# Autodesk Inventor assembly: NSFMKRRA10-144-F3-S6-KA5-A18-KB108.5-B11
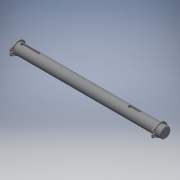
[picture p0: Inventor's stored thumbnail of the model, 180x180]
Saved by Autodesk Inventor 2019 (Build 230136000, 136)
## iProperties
Category: PARTsolutions
Company: MISUMI
Created: 2022-11
Part Number: NSFMKRRA10-144-F3-S6-KA5-A18-KB108.5-B11
Catalog Web Link: www.cadenas.de
Description: NSFMKRR, SFMKRR, PSFMKRR, SSFMKRR, NSFHKRR, SFHKRR, PSFHKRR, SSFHKRR, NSFGKRR, SFGKRR, PSFGKRR, SSFGKRR, NSFMKRRA, SFMKRRA, PSFMKRRA, SSFMKRRA, NSFHKRRA, SFHKRR
Vendor: MISUMI
Document SubType Name: Assembly
Designer: psAdmin
Manufacturer: MISUMI
Mass: 11.263 g
Surface Area: 51.9426 cm^2
Volume: 11.263 cm^3
Density: 1 g/cm^3
Title: NSFMKRRA10-144-F3-S6-KA5-A18-KB108.5-B11
Author: Cadenas PARTsolutions
Comments: Rotary Shafts - Retaining Ring Grooves on Both Ends with Keyway -
PSOL_IDENT_0: {$CADENAS_DATA/23d-libs/misumi/metric/11_rotary_shafts/psfgkrr_asmtab.prj},644 {VTYP=3D},{STYP=ASSTA
PSOL_IDENT_1: B},{NB=NSFMKRRA10-144-F3-S6-KA5-A18-KB108.5-B11},{LINA=NSFMKRRA10-144-F3-S6-KA5-A18-KB108.5-B11},{NN=
PSOL_IDENT_2: NSFMKRR, SFMKRR, PSFMKRR, SSFMKRR, NSFHKRR, SFHKRR, PSFHKRR, SSFHKRR, NSFGKRR, SFGKRR, PSFGKRR, SSFG
PSOL_IDENT_3: KRR, NSFMKRRA, SFMKRRA, PSFMKRRA, SSFMKRRA, NSFHKRRA, SFHKRRA, PSFHKRRA, SSFHKRRA, NSFGKRRA, SFGKRRA
PSOL_IDENT_4: , PSFGKRRA, SSFGKRRA},{DATE=25.01.2022 23:09:58},{GEOMDATE=05.02.2021 08:16:43},{VERSION=},{LINEID=3
PSOL_IDENT_5: 0},{WBVAR=TS,TYS,MAT,ST,ALT1,L,F,S,NOK,KA,A,KB,B,KC,C,ALT3,FC,GALT3,WFC,J,WALT3,V,ALT4,SFC,SG,AG,ALT
PSOL_IDENT_6: 10,KWC,ALT11,WC,ALT5,UC,ALT7,SC,ALT32,CD},{WBNUMERIC=L,F,S,KA,A,KB,B,KC,C,FC,GALT3,WFC,J,WALT3,V,SFC
PSOL_IDENT_7: ,SG,AG,KWC,WC,UC,SC}  {NB=NSFMKRRA10-144-F3-S6-KA5-A18-KB108.5-B11},{LINA=NSFMKRRA10-144-F3-S6-KA5-A
PSOL_IDENT_8: 18-KB108.5-B11},{KT=DUMMY},{PN=NSFMKRRA10-144-F3-S6-KA5-A18-KB108.5-B11},{TS=A},{TSALG='','Standard'
PSOL_IDENT_9: ,'A','Retaining Ring'},{TYS=M},{TYSALG= 'M','h9 (Cold-drawn)','H','h7 (Ground)','G','g6 (Ground)' },
PSOL_IDENT_10: {MAT=S45C},{MATALG= 'S45C','S45C Equivalent', 'SUS304','304 Stainless Steel' },{ST=},{STALG= '','-','
PSOL_IDENT_11: BO','Black Oxide', 'ENP','Electroless Nickel Plating' },{TYPE=NSFMKRR},{D=10},{ALT1=},{LKCMAX=799.9}
PSOL_IDENT_12: ,{L=144.0},{LALG=[15:800/0.1]},{LMIN=15},{LMAX=800},{F=3.0},{FALG=[3:139/0.1]},{FMIN=3},{FMAX1=135.8
PSOL_IDENT_13: },{FMIN2=6.2},{FMAX2=139},{S=6.0},{SALG=[3:139/0.1]},{SMIN1=3},{SMAX1=134},{SMIN2=6.2},{SMAX2=139},{
PSOL_IDENT_14: DD=9.6},{MM=1.15},{MMALG=1.2},{MMJ=2},{NOK=2},{NOKALG= '1', 'with 1 Key Groove', '2'  , 'with 2 Key
PSOL_IDENT_15: Grooves', '3'  , 'with 3 Key Grooves'},{CIFNOK1=0},{CIFNOK2=3},{CIFNOK3=0},{TOL1=0},{TOL2=3},{TOL3=0
PSOL_IDENT_16: },{BB=3},{TT=1.8},{KA=5.0},{KAALG=[5:128/0.1]},{KAMIN1=0},{KAMIN2=5},{KAMIN3=141.2},{KAMAX1=-1000},{
PSOL_IDENT_17: KAMAX2=128},{KAMAX3=-1000},{A=18.0},{AALG=[3:100/0.1]},{AMIN=3},{AMAX=100},{AMAX1=-1000},{AMAX2=100}
PSOL_IDENT_18: ,{AMAX3=-1000},{KAPN=-KA5-A18},{KB=108.5},{KBALG=[25:133/0.1]},{KBMIN1=25},{KBMIN2=25},{KBMIN3=141.2
PSOL_IDENT_19: },{KBMAX1=-1000},{KBMAX2=133},{KBMAX3=-1000},{B=11.0},{BALG=[3:27.5/0.1]},{BMIN=3},{BMAX=27.5},{BMAX
PSOL_IDENT_20: 1=-1000},{BMAX2=27.5},{BMAX3=-1000},{KBPN=-KB108.5-B11},{KC=0.0},{KCALG=[0]},{KCMIN1=121.5},{KCMIN2=
PSOL_IDENT_21: 121.5},{KCMIN3=141.2},{KCMAX1=-1000},{KCMAX2=-1000},{KCMAX3=-1000},{C=0.0},{CALG=0},{CMIN=3},{CMAX=-
PSOL_IDENT_22: 1000},{CMAX1=-1000},{CMAX2=-1000},{CMAX3=-1000},{CIFKA=5},{CIFKB=3},{CIFKC=3},{KCPN=},{ALT3=},{ALT3A
PSOL_IDENT_23: LG= '', 'w/o Set Screw Flat','FC','with FC (Adds a Set Screw Flat)','WFC','with WFC (Adds Two Set Sc
PSOL_IDENT_24: rew Flats)','FCWFC','with FC + WFC (Adds Three Set Screw Flats)' },{ALT3PN=},{FC=0},{FCALG=[0]},{FCM
PSOL_IDENT_25: IN=0},{FCMAX=143},{GALT3=0},{GALT3ALG=[0]},{GALT3MIN=1},{GALT3MAX=70},{GALT3MAX2=70},{GALT3MAX3=70},
PSOL_IDENT_26: {WFC=0},{WFCALG=[0]},{WFCMIN=0},{WFCMIN2=2},{WFCMAX=140},{WFCMAX2=-3},{WFCMAX3=-4},{J=0},{JALG=[0]},
PSOL_IDENT_27: {JMIN=1},{JMAX=70},{JMAX2=-2},{JMAX3=-5},{WALT3=0},{WALT3ALG=[0]},{WALT3MIN=0},{WALT3MIN2=146},{WALT
PSOL_IDENT_28: 3MAX=141},{WALT3MAX2=141},{V=0},{VALG=[0]},{VMIN=1},{VMAX=70},{VMAX2=70},{CIFFC=0},{ALT4=},{ALT4ALG=
PSOL_IDENT_29: '', 'w/o SFC (2 Set Screw Flats (Angle Specified))', 'SFC'  , 'with SFC (2 Set Screw Flats (Angle S
PSOL_IDENT_30: pecified))'},{ALT4PN=},{SFC=0},{SFCALG=[0]},{SFCMIN=0},{SFCMAX=143},{SG=0},{SGALG=[0]},{SGMIN=1},{SG
PSOL_IDENT_31: MAX=70},{AG=0},{AGALG=[0]},{H=0},{CIFSFC=0},{ALT10=},{ALT10ALG= '','Not applicable' },{KWC=0},{KWCAL
PSOL_IDENT_32: G=[0]},{KWCMIN=1},{KWCMAX=0},{WALT10=8},{ALT10PN=},{ALT11=},{ALT11ALG= '','Not applicable' },{WC=0.0
PSOL_IDENT_33: },{WCALG=[0]},{ALT11PN=},{ALT5=},{ALT5ALG= '', 'w/o UC (Slit Cam Groove)', 'UC', 'with UC (Slit Cam
PSOL_IDENT_34: Groove)'},{ALT5PN=},{UC=0},{UCALG=[0]},{UCMIN=1},{UCMAX=138},{DDALT5=0},{LL1=0},{ALT7=},{ALT7ALG= ''
PSOL_IDENT_35: , 'w/o SC (Wrench Flats)', 'SC', 'with SC (Wrench Flats)'},{ALT7PN=},{SC=0},{SCALG=[0]},{SCMIN=0},{S
PSOL_IDENT_36: CMAX=136},{LL2=0},{LL2ALG=8},{WALT7=0},{CIFSC=0},{ALT32=},{ALT32ALG= '','w/o CD (Changes Part D Cham
PSOL_IDENT_37: fering)','CD','with CD (Changes Part D Chamfering)' },{CD=},{CDALG= '','N/A' },{CD3D=0.5},{ALT32PN=}
PSOL_IDENT_38: ,{CIF323R=0},{CIF323L=0},{CIF324R=0},{CIF324L=0},{CIF3210=0},{CIF32F=0},{CIF32S=0},{ERRORPN=},{ERROR
PSOL_IDENT_39: KGALT3=OK},{ERRORKGALT4=OK},{ERRORKGALT5=OK},{ERRORKGALT7=OK},{ERRORKGALT10=OK},{ERRORRALT3=OK},{ERR
PSOL_IDENT_40: ORRALT4=NG},{ERRORRALT5=NG},{ERRORRALT7=NG},{ERRORRALT10=OK},{ERRORALT34=OK},{ERRORALT35=OK},{ERRORA
PSOL_IDENT_41: LT37=OK},{ERRORALT310=OK},{ERRORALT45=OK},{ERRORALT47=OK},{ERRORALT410=OK},{ERRORALT57=OK},{ERRORALT
PSOL_IDENT_42: 510=OK},{ERRORALT710=OK},{PCUT3D=0},{QCUT3D=0},{TTALT2=1.8},{BBALT2=3},{PPATH=11_components/psfgkrr/
PSOL_IDENT_43: psfgkrr_asmtpl.prj}
NB: NSFMKRRA10-144-F3-S6-KA5-A18-KB108.5-B11
NN: NSFMKRR, SFMKRR, PSFMKRR, SSFMKRR, NSFHKRR, SFHKRR, PSFHKRR, SSFHKRR, NSFGKRR, SFGKRR, PSFGKRR, SSFGKRR, NSFMKRRA, SFMKRRA, PSFMKRRA, SSFMKRRA, NSFHKRRA, SFHKRR
NT: Rotary Shafts - Retaining Ring Grooves on Both Ends with Keyway -
NBSYN: $PN.
LINA: NSFMKRRA10-144-F3-S6-KA5-A18-KB108.5-B11
CATALOG: Misumi
PN: NSFMKRRA10-144-F3-S6-KA5-A18-KB108.5-B11
TS: Retaining Ring
TYS: h9 (Cold-drawn)
MAT: S45C Equivalent
ST: -
D: 10
ALT1: w/o LKC (Changes L Tolerance)
L: 144
F: 3
S: 6
DD: 9.6
MM: 1.15
NOK: with 2 Key Grooves
KA: 5
A: 18
KB: 108.5
B: 11
KC: 0
C: 0
ALT3: w/o Set Screw Flat
FC: 0
GALT3: 0
WFC: 0
J: 0
WALT3: 0
V: 0
ALT4: w/o SFC (2 Set Screw Flats (Angle Specified))
SFC: 0
SG: 0
AG: 0
H: 0
ALT10: Not applicable
KWC: 0
ALT11: Not applicable
WC: 0
ALT5: w/o UC (Slit Cam Groove)
UC: 0
DDALT5: 0
LL1: 0
ALT7: w/o SC (Wrench Flats)
SC: 0
LL2: 0
WALT7: 0
ALT32: w/o CD (Changes Part D Chamfering)
CD: N/A
SUPPLIER: MISUMI
ARTICLENO: NSFMKRRA10-144-F3-S6-KA5-A18-KB108.5-B11
BOMINFO: NSFMKRRA10-144-F3-S6-KA5-A18-KB108.5-B11
CREATOR: CADENAS GmbH
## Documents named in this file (3)
- e:\temp\worker_COMMON_2\temp\tmp_7896_20_snJjB\format_0\NSFMKRRA10-144-F3-S6-KA5-A18-KB108_5-B11.iam
- e:\temp\worker_COMMON_2\temp\tmp_7896_20_snJjB\format_0\NSFMKRRA10-144-F3-S6-KA5-A18-KB108_5-B11_s.ipt
- e:\temp\worker_COMMON_2\temp\tmp_7896_20_snJjB\format_0\STWS10.ipt
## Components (3 placed, 2 different names)
1. NSFMKRRA10-144-F3-S6-KA5-A18-KB108_5-B11_s:1 — to_rring_1_XY@1 <-> 1_XY@2, to_rring_1_Z@1 <-> 1_Z@2, to_rring_1_YZ@1 <-> 1_YZ@2, to_rring_2_XY@1 <-> 1_XY@3, to_rring_2_Z@1 <-> 1_Z@3, to_rring_2_YZ@1 <-> 1_YZ@3
2. STWS10:1 — to_rring_1_XY@1 <-> 1_XY@2, to_rring_1_Z@1 <-> 1_Z@2, to_rring_1_YZ@1 <-> 1_YZ@2
3. STWS10:2 — to_rring_2_XY@1 <-> 1_XY@3, to_rring_2_Z@1 <-> 1_Z@3, to_rring_2_YZ@1 <-> 1_YZ@3
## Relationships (6: Mate 4, Angle 2)
- to_rring_1_XY@1 <-> 1_XY@2 [Mate]: NSFMKRRA10-144-F3-S6-KA5-A18-KB108_5-B11_s:1 ↔ STWS10:1
- to_rring_1_Z@1 <-> 1_Z@2 [Mate]: NSFMKRRA10-144-F3-S6-KA5-A18-KB108_5-B11_s:1 ↔ STWS10:1
- to_rring_1_YZ@1 <-> 1_YZ@2 [Angle]: NSFMKRRA10-144-F3-S6-KA5-A18-KB108_5-B11_s:1 ↔ STWS10:1
- to_rring_2_XY@1 <-> 1_XY@3 [Mate]: NSFMKRRA10-144-F3-S6-KA5-A18-KB108_5-B11_s:1 ↔ STWS10:2
- to_rring_2_Z@1 <-> 1_Z@3 [Mate]: NSFMKRRA10-144-F3-S6-KA5-A18-KB108_5-B11_s:1 ↔ STWS10:2
- to_rring_2_YZ@1 <-> 1_YZ@3 [Angle]: NSFMKRRA10-144-F3-S6-KA5-A18-KB108_5-B11_s:1 ↔ STWS10:2
